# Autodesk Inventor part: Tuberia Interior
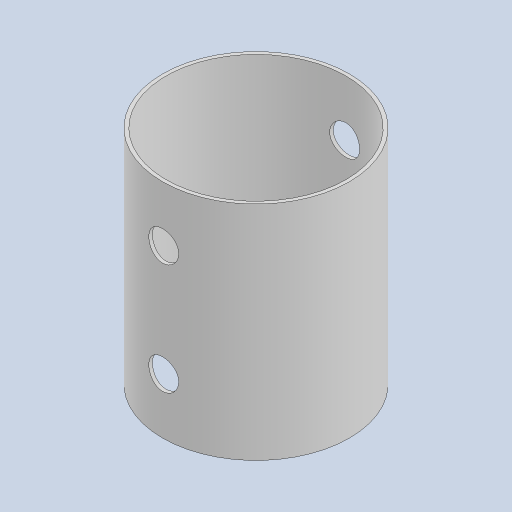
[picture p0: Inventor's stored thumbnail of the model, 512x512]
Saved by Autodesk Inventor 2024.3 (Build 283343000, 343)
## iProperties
Created: 2025-10
Part Number: Tuberia Interior
Material: Genérico
Document SubType Name: Modeling
Designer: Asus
Density: 1 g/cm^3
Appearance: Valor por defecto
Author: Asus
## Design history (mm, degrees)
sketch "Boceto1"
  geometry: C1 r 84.138 at (0, 0); C2 r 77.028 at (0, 0); 1 further point
  constraints: 2 centre point, 2 coincident
  dimensions: "d0" = 168.275 diameter of C1; "d1" = 7.11 radial gap between concentric circles of C1 C2
extrude "Extrusión1" new body sketch "Boceto1" distance "d2" = 200; taper "d3" = 0 deg
sketch "Boceto2"
  geometry: C1 r 81 at (0, 0); 1 further point
  constraints: 1 centre point, 1 coincident
  dimensions: "d4" = 162 diameter of C1
extrude "Extrusión2" cut sketch "Boceto2" extent not by distance; stored distance "d5" = 200; taper "d6" = 0 deg
node "Plano de trabajo1"
sketch "Boceto3"
  geometry: L1 (0, 240)-(0, -40) reference; L2 (84.138, 200)-(-84.138, 200) reference; L3 (84.138, 0)-(-84.138, 0) reference; 3 further points
  dimensions: "d7" = 0 distance from line of L1 point (0, 150); "d8" = 0 distance from line of L1 point (0, 50) (computed from d7); "d9" = 50 distance from line of point (0, 150) L2 (= d10); "d10" = 50 distance from line of L3 point (0, 50); "d11" = 100 distance of point (0, 50) point (0, 150) (derived)
hole "Agujero1" sketch "Boceto3" at (0, 150), (0, 50) diameter "d12" = 27; stored, may be unused: countersink angle "d16" = 90 deg, drill point angle "d18" = 118 deg; dims "d13" = 6, "d14" = 4, "d15" = 2, "d17" = 8
node "Sólido1"
